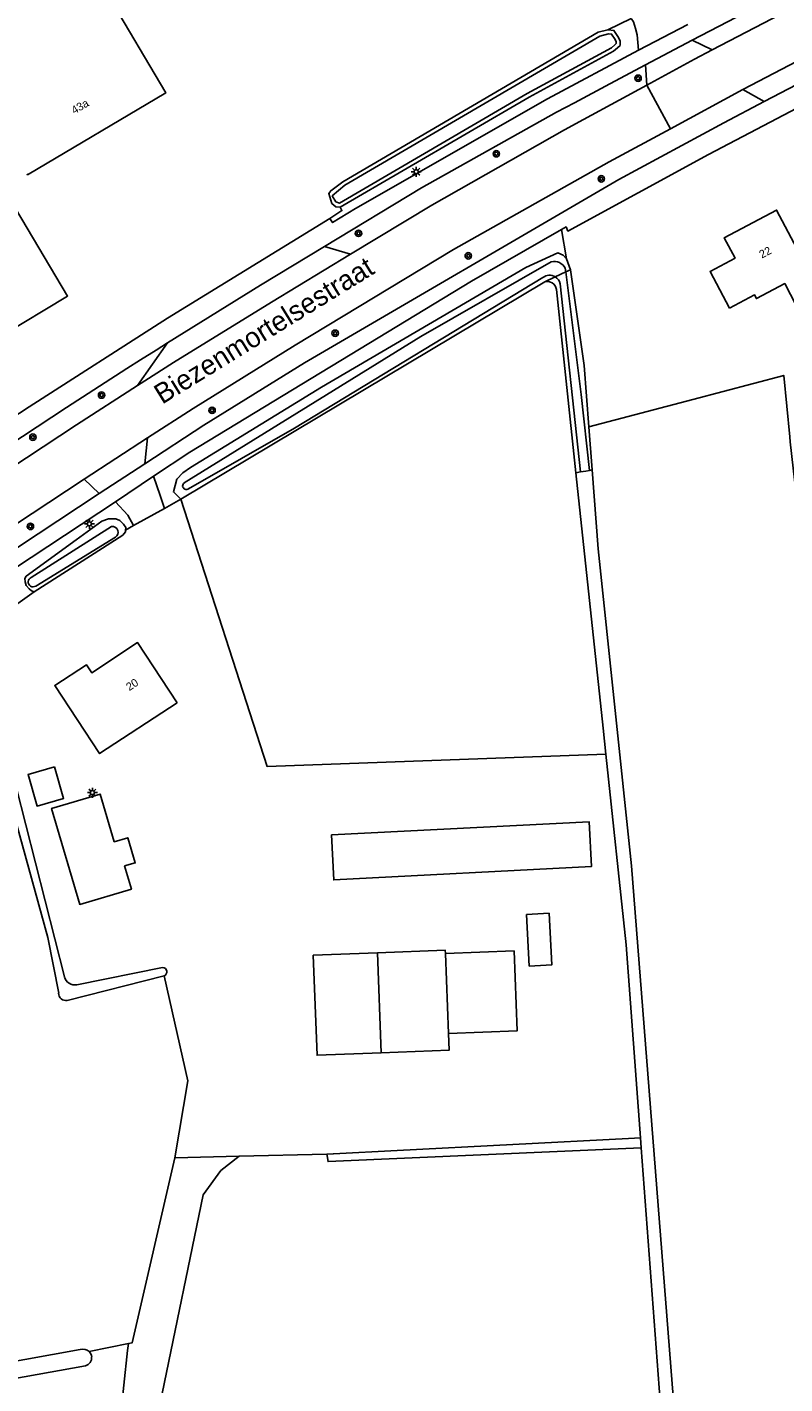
# Model space of a CAD drawing. Extents: x 140000 to 143000, y 403500 to 406000.
# Drawn here: x 140845.6 to 140940.3, y 404635.1 to 404804.7 of the extents above; entities that cross this region are included whole.
import ezdxf

# ---------------------------------------------------------------- set-up
doc = ezdxf.new("R2010")
doc.units = 0
for name, color, linetype in [('gg-afsc-erfafscheiding', 7, 'Continuous'), ('gg-anno-huisnummerreeks BGT', 7, 'Continuous'), ('gg-anno-openbare ruimte label', 7, 'Continuous'), ('gg-bbg-bassin', 7, 'Continuous'), ('gg-bbg-bijgebouw', 7, 'Continuous'), ('gg-bbg-gedigitaliseerde bijgebouw', 7, 'Continuous'), ('gg-bbg-hoofdgebouw', 7, 'Continuous'), ('gg-bbg-luifel en loopbrug', 7, 'Continuous'), ('gg-knt-bronhoudergrens', 7, 'Continuous'), ('gg-knt-verharding', 7, 'Continuous'), ('gg-knt-verharding nz', 7, 'Continuous'), ('gg-kntw-bovenkant insteek waterloop', 7, 'Continuous'), ('gg-kntw-waterlijn', 7, 'Continuous'), ('gt-grn-groengrens', 7, 'Continuous'), ('gt-grn-vlakafsluiter', 7, 'Continuous'), ('gt-grn-weggrens', 7, 'Continuous'), ('gt-symb-boom', 7, 'Continuous'), ('gt-symb-lichtmast', 7, 'Continuous')]:
    doc.layers.add(name, color=color, linetype=linetype)

# ---------------------------------------------------------------- blocks, each defined once
blk = doc.blocks.new('gt0-BOOM')
at = {"layer": 'gt-symb-boom'}
for radius in [0.4, 0.2]:
    blk.add_circle((0, 0), radius, dxfattribs=at)
blk = doc.blocks.new('gt0-LMAST')
at = {"layer": 'gt-symb-lichtmast'}
for p, q in [((-0.18, 0.17), (-0.45, 0.44)), ((-0.01, 0.25), (-0.01, 0.62)), ((0.17, 0.17), (0.44, 0.44)), ((-0.26, 0), (-0.63, 0)), ((-0.18, -0.18), (-0.45, -0.45)), ((-0.01, -0.25), (-0.01, -0.63)), ((0.44, -0.45), (0.17, -0.18)), ((0.24, 0), (0.62, 0))]:
    blk.add_line(p, q, dxfattribs=at)
blk.add_circle((-0.01, 0), 0.25, dxfattribs=at)

msp = doc.modelspace()

# ---------------------------------------------------------------- linework, layer by layer
at = {"layer": 'gg-afsc-erfafscheiding'}
for p, q in [((140918.17, 404804.33), (140921.11, 404805.75)), ((140912.41, 404779.39), (140913.01, 404775.71)), ((140857.92, 404741.81), (140858.94, 404742.41)), ((140841.52, 404730.56), (140846.51, 404734.12))]:
    msp.add_line(p, q, dxfattribs=at)
for points in [[(140883.47, 404780.75), (140884.96, 404781.74), (140884.76, 404782.18)], [(140922.28, 404665.89), (140920.75, 404665.8), (140891.86, 404664.29), (140883.9, 404663.87), (140883.85, 404663.87), (140883.09, 404663.85)], [(140874, 404446.51), (140870.26, 404474.1), (140864.71, 404531.22), (140862.31, 404553.57), (140861.92, 404555.16), (140857.7, 404612.34), (140857.26, 404630.62), (140858.18, 404639.3), (140858.28, 404640.16)]]:
    msp.add_lwpolyline(points, dxfattribs=at)
at = {"layer": 'gg-bbg-bassin'}
msp.add_lwpolyline([(140883.66, 404703.74), (140915.85, 404705.38), (140916.14, 404699.76), (140883.95, 404698.11), (140883.66, 404703.74)], dxfattribs=at)
at = {"layer": 'gg-bbg-bijgebouw'}
msp.add_lwpolyline([(140857.81, 404699.85), (140859.13, 404700.23), (140858.21, 404703.38), (140856.51, 404702.88), (140854.76, 404708.82), (140848.68, 404707.04), (140852.21, 404695.05), (140858.67, 404696.95), (140857.81, 404699.85)], dxfattribs=at)
at = {"layer": 'gg-bbg-gedigitaliseerde bijgebouw'}
for p, q in [((140881.38, 404688.68), (140889.4, 404688.99)), ((140889.4, 404688.99), (140889.87, 404676.5))]:
    msp.add_line(p, q, dxfattribs=at)
for points in [[(140908.03, 404693.78), (140908.37, 404687.34), (140911.19, 404687.49), (140910.85, 404693.93), (140908.03, 404693.78)], [(140881.38, 404688.68), (140881.86, 404676.19), (140889.87, 404676.5)]]:
    msp.add_lwpolyline(points, dxfattribs=at)
at = {"layer": 'gg-bbg-hoofdgebouw'}
for points in [[(140831.15, 404810.59), (140848.53, 404820.83), (140862.94, 404796.45), (140845.69, 404786.22), (140845.62, 404786.34)], [(140840.1, 404780.23), (140842.41, 404776.31), (140837.89, 404773.62), (140842.39, 404766.05), (140850.68, 404771.06), (140844.17, 404782.02)], [(140933.4, 404769.55), (140936.52, 404771.2), (140936.76, 404770.75), (140940.3, 404772.62), (140941.74, 404769.9), (140944.74, 404771.49), (140939.28, 404781.81), (140932.74, 404778.35), (140934.09, 404775.8), (140930.97, 404774.15), (140933.4, 404769.55)], [(140864.37, 404720.24), (140859.43, 404727.76), (140853.71, 404723.99), (140853.03, 404725), (140849.09, 404722.4), (140854.69, 404713.88), (140864.37, 404720.24)]]:
    msp.add_lwpolyline(points, dxfattribs=at)
at = {"layer": 'gg-bbg-luifel en loopbrug'}
msp.add_line((140897.89, 404688.91), (140898.27, 404678.92), dxfattribs=at)
for points in [[(140849.05, 404712.24), (140845.74, 404711.29), (140846.88, 404707.33), (140850.19, 404708.28), (140849.05, 404712.24)], [(140889.4, 404688.99), (140897.87, 404689.31), (140897.89, 404688.91)], [(140897.89, 404688.91), (140906.48, 404689.24), (140906.86, 404679.25), (140898.27, 404678.92)], [(140898.27, 404678.92), (140898.35, 404676.82), (140889.87, 404676.5)]]:
    msp.add_lwpolyline(points, dxfattribs=at)
at = {"layer": 'gg-knt-bronhoudergrens'}
for points in [[(140964.61, 404717.97), (140962.98, 404731.14), (140958.32, 404731.97), (140955.53, 404731.82), (140951.06, 404731.35), (140943.53, 404730.57), (140940.99, 404752.83), (140940.93, 404753.47), (140940.16, 404761.14), (140928.81, 404758.14), (140915.82, 404754.71)], [(140917.95, 404713.8), (140875.63, 404712.26), (140864.84, 404745.67)], [(140862.74, 404686.11), (140865.7, 404672.98), (140864.07, 404663.36)], [(140872.14, 404663.57), (140869.84, 404661.78), (140867.61, 404658.77), (140862.49, 404633.91), (140862.76, 404625.44), (140926.68, 404628.99)], [(140922.37, 404664.64), (140883.24, 404662.91), (140883.12, 404663.64), (140883.09, 404663.85)]]:
    msp.add_lwpolyline(points, dxfattribs=at)
at = {"layer": 'gg-knt-verharding'}
for p, q in [((140928.17, 404804.99), (140922.04, 404801.78)), ((140922.89, 404799.97), (140928.71, 404803.04)), ((140928.71, 404803.04), (140931.24, 404801.83)), ((140922.89, 404799.97), (140923.05, 404797.42)), ((140937.71, 404795.37), (140941.81, 404797.52)), ((140935.06, 404796.87), (140926, 404791.97)), ((140937.71, 404795.37), (140935.06, 404796.87)), ((140882.77, 404777.25), (140886.04, 404776.28)), ((140863.16, 404765.2), (140859.43, 404759.87)), ((140860.34, 404750.1), (140860.68, 404753.35)), ((140860.34, 404750.1), (140854.63, 404746.37)), ((140823.53, 404728.93), (140852.74, 404748.19)), ((140852.74, 404748.19), (140854.63, 404746.37)), ((140856.67, 404745.36), (140861.41, 404748.54)), ((140824.81, 404726.72), (140854.63, 404746.37)), ((140823.56, 404723.54), (140856.67, 404745.36)), ((140862.81, 404744.52), (140858.94, 404742.41))]:
    msp.add_line(p, q, dxfattribs=at)
for points in [[(140912.41, 404779.39), (140912.97, 404779.71), (140913.21, 404779.18), (140930.77, 404788.76), (140938.49, 404792.8), (140943.49, 404795.42), (140947.69, 404797.61), (140954.54, 404801.09), (140956.67, 404802.18), (140959.31, 404803.5), (140996.81, 404822.29), (141003.91, 404825.85), (141026.47, 404837.15)], [(140928.71, 404803.04), (140937.54, 404807.63), (140974.97, 404826.51)], [(140974.31, 404823.62), (140938.67, 404805.71), (140931.24, 404801.83)], [(140922.04, 404801.78), (140921.86, 404803.71), (140921.64, 404804.48), (140921.39, 404805.34), (140921.11, 404805.75)], [(140922.04, 404801.78), (140910.64, 404795.72), (140886.66, 404781.99), (140883.79, 404780.24), (140883.47, 404780.75)], [(140882.77, 404777.25), (140894.91, 404784.59), (140911.78, 404794.03), (140914.01, 404795.22), (140918.44, 404797.59), (140922.89, 404799.97)], [(140923.05, 404797.42), (140919.61, 404795.55), (140915.15, 404793.13), (140912.77, 404791.83), (140896.21, 404782.41), (140886.04, 404776.28)], [(140937.71, 404795.37), (140932.7, 404792.73), (140919.58, 404785.63), (140880.27, 404762.71), (140867.71, 404754.91), (140860.34, 404750.1)], [(140926, 404791.97), (140918.34, 404787.83), (140898.92, 404776.88), (140879.11, 404764.91), (140866.37, 404757.03), (140860.68, 404753.35)], [(140883.47, 404780.75), (140863.16, 404768.28), (140845.88, 404757.2), (140833.25, 404748.96), (140833.61, 404748.4), (140833.11, 404748.07)], [(140861.41, 404748.54), (140865.94, 404751.56), (140901.17, 404772.94), (140912.41, 404779.39)], [(140863.16, 404765.2), (140874.77, 404772.42), (140882.77, 404777.25)], [(140812.02, 404731.75), (140850.54, 404757.15), (140858.07, 404761.99), (140859.79, 404763.1), (140861.74, 404764.31), (140863.16, 404765.2)], [(140814.52, 404730.38), (140851.8, 404754.96), (140859.43, 404759.87)], [(140861.41, 404748.54), (140862.25, 404746.14), (140862.81, 404744.52)], [(140856.67, 404745.36), (140858.2, 404743.67), (140858.94, 404742.41)], [(140864.07, 404663.36), (140858.77, 404640.26), (140858.28, 404640.16)]]:
    msp.add_lwpolyline(points, dxfattribs=at)
at = {"layer": 'gg-knt-verharding nz'}
for p, q in [((140941.86, 404800.43), (140935.06, 404796.87)), ((140860.68, 404753.35), (140852.74, 404748.19))]:
    msp.add_line(p, q, dxfattribs=at)
for points in [[(140931.24, 404801.83), (140929.03, 404800.67), (140923.05, 404797.42)], [(140886.04, 404776.28), (140876.15, 404770.32), (140863.9, 404762.75), (140860.34, 404760.46), (140859.43, 404759.87)]]:
    msp.add_lwpolyline(points, dxfattribs=at)
at = {"layer": 'gg-kntw-bovenkant insteek waterloop'}
for p, q in [((140913.01, 404775.71), (140913.52, 404774.36)), ((140911.61, 404773.46), (140910.3, 404772.84)), ((140912.92, 404774.08), (140913.52, 404774.36)), ((140864.84, 404745.67), (140910.3, 404772.84)), ((140914.21, 404748.98), (140911.78, 404771.89)), ((140916.24, 404749.34), (140915.82, 404754.71)), ((140914.21, 404748.98), (140917.61, 404717.06)), ((140839.29, 404729.17), (140850.29, 404685.98)), ((140917.61, 404717.06), (140917.95, 404713.8)), ((140862.56, 404687.16), (140851.84, 404685)), ((140850.65, 404683.05), (140862.74, 404686.11)), ((140922.37, 404664.64), (140922.28, 404665.89)), ((140922.37, 404664.64), (140924.88, 404631.02))]:
    msp.add_line(p, q, dxfattribs=at)
for points in [[(140918.17, 404804.33), (140917, 404804.03), (140885.06, 404785.32), (140883.56, 404784.22), (140883.32, 404783.86), (140883.7, 404782.63), (140884.21, 404782.22), (140884.76, 404782.18)], [(140918.17, 404804.33), (140918.22, 404804.35), (140918.95, 404804.25), (140919.52, 404803.36), (140919.73, 404802.92), (140919.71, 404802.39), (140919.39, 404802.07), (140918.91, 404801.68), (140908.36, 404795.93), (140884.76, 404782.18)], [(140913.01, 404775.71), (140912.62, 404776.17), (140911.92, 404776.48), (140907.95, 404774.64), (140882.42, 404759.67), (140866.06, 404749.62), (140865.1, 404748.96), (140864.33, 404748.18), (140863.91, 404746.59), (140864.84, 404745.67)], [(140913.52, 404774.36), (140915.24, 404762.4), (140915.82, 404754.71)], [(140926.52, 404631.43), (140921.16, 404699.87), (140916.99, 404739.47), (140916.24, 404749.34)], [(140846.51, 404734.12), (140846.19, 404734.21), (140845.89, 404734.47), (140845.49, 404734.91), (140845.37, 404735.36), (140845.33, 404735.77), (140845.5, 404736.05), (140851.76, 404740.6), (140854.95, 404742.95), (140855.8, 404743.23), (140856.72, 404743.22), (140857.21, 404743.03), (140857.68, 404742.56), (140857.95, 404742.15), (140857.92, 404741.81)], [(140846.51, 404734.12), (140857.59, 404741.19), (140857.91, 404741.62), (140857.92, 404741.81)], [(140837.9, 404728.28), (140848.23, 404690.91), (140849.57, 404683.94)], [(140917.95, 404713.8), (140920.48, 404690), (140922.28, 404665.89)], [(140852.27, 404639.42), (140802.45, 404630.41), (140706.44, 404612.8)], [(140706.96, 404610.44), (140759.3, 404620.58), (140852.93, 404637.38)]]:
    msp.add_lwpolyline(points, dxfattribs=at)
for centre, radius, start, end in [((140910.63, 404771.74), 1.15, 7.5586, 106.9749), ((140862.55, 404686.62), 0.542, 289.9134, 89.1879), ((140851.62, 404686.37), 1.39, 196.6491, 278.9417), ((140850.46, 404683.93), 0.894, 179.0094, 281.9042), ((140852.62, 404638.4), 1.07, 44.8854, 108.9742), ((140852.62, 404638.4), 1.07, 286.845, 5.6347), ((140852.62, 404638.4), 1.08, 5.7797, 44.8597)]:
    msp.add_arc(centre, radius, start, end, dxfattribs=at)
at = {"layer": 'gg-kntw-waterlijn'}
for p, q in [((140912.86, 404774.54), (140912.92, 404774.08)), ((140914.79, 404749.08), (140912.23, 404772.6)), ((140914.79, 404749.08), (140914.21, 404748.98)), ((140915.88, 404749.28), (140916.24, 404749.34)), ((140856.18, 404742.26), (140846.14, 404735.9)), ((140846.7, 404734.82), (140856.67, 404740.92))]:
    msp.add_line(p, q, dxfattribs=at)
for points in [[(140884.21, 404782.85), (140884.64, 404782.69), (140908.11, 404796.36), (140918.63, 404802.1), (140919.06, 404802.44), (140919.22, 404802.61), (140919.23, 404802.82), (140919.09, 404803.11), (140918.65, 404803.79), (140918.26, 404803.84), (140917.19, 404803.56), (140885.34, 404784.9), (140883.75, 404783.58), (140884.21, 404782.85)], [(140911.12, 404775.36), (140894.81, 404765.99), (140865.27, 404747.74)], [(140865.81, 404746.99), (140879.05, 404754.57), (140910.05, 404773.37)], [(140912.92, 404774.08), (140914.86, 404758.77), (140915.88, 404749.28)]]:
    msp.add_lwpolyline(points, dxfattribs=at)
for centre, radius, start, end in [((140911.45, 404773.8), 1.59, 27.4103, 101.9284), ((140910.9, 404772.3), 1.36, 58.456, 128.2338), ((140910.9, 404772.3), 1.36, 12.9556, 58.5239), ((140865.52, 404747.35), 0.46, 121.8382, 310.2533), ((140856.27, 404741.53), 0.735, 302.9378, 97.0694), ((140846.37, 404735.33), 0.605, 111.7198, 302.7293)]:
    msp.add_arc(centre, radius, start, end, dxfattribs=at)
at = {"layer": 'gt-grn-groengrens'}
for p, q in [((140862.81, 404744.52), (140864.84, 404745.67)), ((140853.38, 404639.16), (140858.28, 404640.16))]:
    msp.add_line(p, q, dxfattribs=at)
at = {"layer": 'gt-grn-vlakafsluiter'}
for p, q in [((140911.61, 404773.46), (140912.92, 404774.08)), ((140872.14, 404663.57), (140864.07, 404663.36)), ((140883.09, 404663.85), (140872.14, 404663.57))]:
    msp.add_line(p, q, dxfattribs=at)
msp.add_lwpolyline([(140915.88, 404749.28), (140915.44, 404749.2), (140914.79, 404749.08)], dxfattribs=at)
at = {"layer": 'gt-grn-weggrens'}
msp.add_line((140926, 404791.97), (140923.05, 404797.42), dxfattribs=at)

# ---------------------------------------------------------------- block references
at = {"layer": 'gt-symb-boom'}
for p in [(140921.97, 404798.28), (140904.25, 404788.84), (140917.37, 404785.71), (140887.03, 404778.9), (140900.75, 404776.09), (140884.12, 404766.42), (140854.93, 404758.69), (140868.74, 404756.78), (140846.35, 404753.43), (140846.04, 404742.28)]:
    msp.add_blockref('gt0-BOOM', p, dxfattribs=at)
at = {"layer": 'gt-symb-lichtmast'}
for p in [(140894.25, 404786.6), (140853.42, 404742.6), (140853.79, 404709.01)]:
    msp.add_blockref('gt0-LMAST', p, dxfattribs=at)

# ---------------------------------------------------------------- texts
at = {"layer": 'gg-anno-huisnummerreeks BGT'}
for s, rotation, p in [('43a', 30.7, (140851.53, 404793.75)), ('22', 27.9, (140937.43, 404775.74)), ('20', 33.4, (140858.4, 404721.69))]:
    msp.add_text(s, height=1, rotation=rotation, dxfattribs=at).set_placement(p)
at = {"layer": 'gg-anno-openbare ruimte label'}
msp.add_text('Biezenmortelsestraat', height=2.5, rotation=31.7, dxfattribs=at).set_placement((140862.5, 404757.48))

doc.saveas('drawing.dxf')
